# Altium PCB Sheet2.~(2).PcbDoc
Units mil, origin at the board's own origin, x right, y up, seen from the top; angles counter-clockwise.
Board outline 6000 x 4000 mil, 2 copper layers (Top Layer, Bottom Layer); 4 components, 14 nets, 12 pads, 0 vias.
Unrouted connection lines stored in the file: 6.
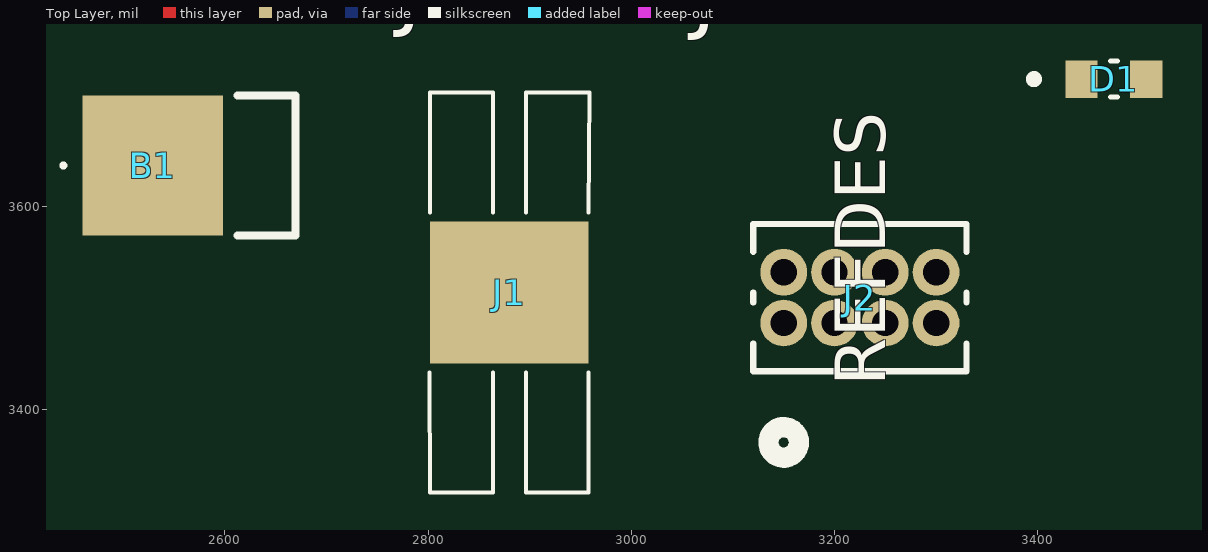
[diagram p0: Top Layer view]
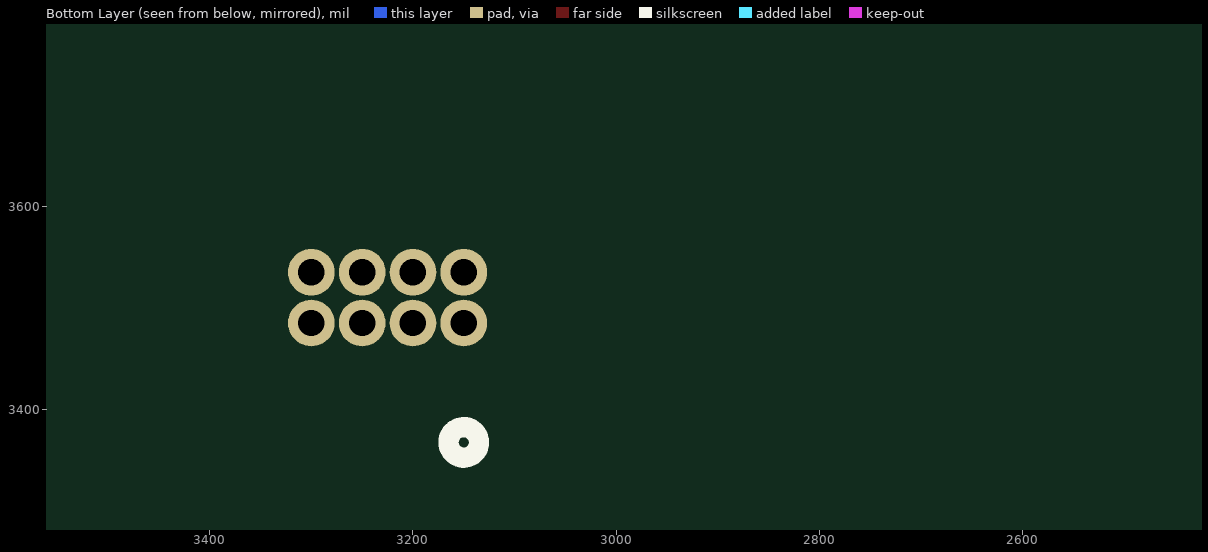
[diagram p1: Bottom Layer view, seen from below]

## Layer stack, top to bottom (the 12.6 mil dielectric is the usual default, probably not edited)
Top Solder: solder mask 0.4, Solder Resist, Dk 3.5
Top Layer: signal copper 1.4
Dielectric 1: dielectric 12.6, FR-4, Dk 4.8
Bottom Layer: signal copper 1.4
Bottom Solder: solder mask 0.4, Solder Resist, Dk 3.5

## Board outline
1000,1000 7000,1000 7000,5000 1000,5000

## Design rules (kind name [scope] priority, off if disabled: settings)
Clearance [All] p1: gap=10 ignorepadtopadclearanceinfootprint=FALSE except(0: Arc-Hole Track-Hole SMDPad-Hole THPad-Hole Via-Hole Fill-Hole Poly-Hole Region-Hole Text-Hole)
PolygonConnect [All] p1: connectstyle=Relief reliefconductorwidth=10 reliefentries=4 polygonreliefangle="90 Angle" airgapwidth=10
RoomDefinition Sheet2 [InComponentClass('Sheet2')] p1: confinementstyle=ConfineIn formatcopy=TRUE lockcomponents=FALSE outline 2410,3270 3540,3270 3540,3860 2410,3860
RoutingVias [All] p1: holewidth=28 width=50 viastyle="Through Hole" minholewidth=28 minwidth=50 maxholewidth=28 maxwidth=50
SolderMaskExpansion [All] p1: expansion=4 istentingtop=FALSE
Width [All] p1: maxlimit=10 minlimit=10 preferedwidth=10
30 further rules are at their usual default settings.

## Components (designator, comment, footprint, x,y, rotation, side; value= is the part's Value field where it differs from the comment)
B1 "110" 110 2565,3640 r0 top
D1 "LTST-C190KRKT" LEDC1608X35N 3475,3725 r0 top
J1 "112" 112 2880,3515 r90 top
J2 "20021111-00008T4LF" CONN_20021111-00008T4LF_AMP 3150,3485 r90 top

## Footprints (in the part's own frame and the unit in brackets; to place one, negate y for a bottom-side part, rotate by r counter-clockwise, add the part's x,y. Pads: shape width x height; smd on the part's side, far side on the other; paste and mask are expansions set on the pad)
110 [mm]
  rect 3.51x3.51 smd: 1(-0.915,0)
  silkscreen extent -3.2,-1.76 2.66,1.76
112 [mm]
  rect 3.56x3.96 smd: 1(0,0)
  silkscreen extent -5,-2 5,2
CONN_20021111-00008T4LF_AMP [mil]
  round 46 / inner round 60 / far side round 46 hole 26 paste-23 mask+0: 1(0,0) 2(50,0) 3(0,-50) 4(50,-50) 5(0,-100) 6(50,-100) 7(0,-150) 8(50,-150)
  silkscreen extent -133,-180 98,30
LEDC1608X35N [mm]
  rect 0.81x0.93 smd: A(0.81,0) C(-0.81,0)
  silkscreen extent -2.1,-0.45 0.09,0.45, body extent -0.8,-0.4 0.8,0.4, height 0.8

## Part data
B1: "Battery Contacts S/M COIN CELL CNCT POSITIVE 16mm UP", Manufacturer_Name="Keystone Electronics", Mouser Part Number=534-110
D1: "Red 631nm LED Indication - Discrete 2V 0603 (1608 Metric)", Package="0603 Lite-On"
J1: "Battery Contacts S/M COIN CELL CNCT NEGATIVE 16mm UP", Manufacturer_Name="Keystone Electronics", Mouser Part Number=534-112
J2: "No Description Available", Mfr_Name="Amphenol ICC"

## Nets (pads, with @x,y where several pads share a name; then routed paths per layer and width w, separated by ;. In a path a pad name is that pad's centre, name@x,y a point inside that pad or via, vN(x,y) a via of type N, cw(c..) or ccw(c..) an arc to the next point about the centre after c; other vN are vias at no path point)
GND: D1.C J1.1 J2.1 J2.2 J2.3 J2.7
NetC1_1: 
NetC1_2: 
NetD1_A: D1.A
NetL1_2: 
NetR1_1: 
OSC32_IN: 
OSC32_OUT: 
OSCIN: 
OSCOUT: 
RST: J2.4
SWCLK: J2.5
SWDIO: J2.6
VDDSD: B1.1 J2.8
